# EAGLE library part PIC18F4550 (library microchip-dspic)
PIC18F Flash Microcontroller with USB port
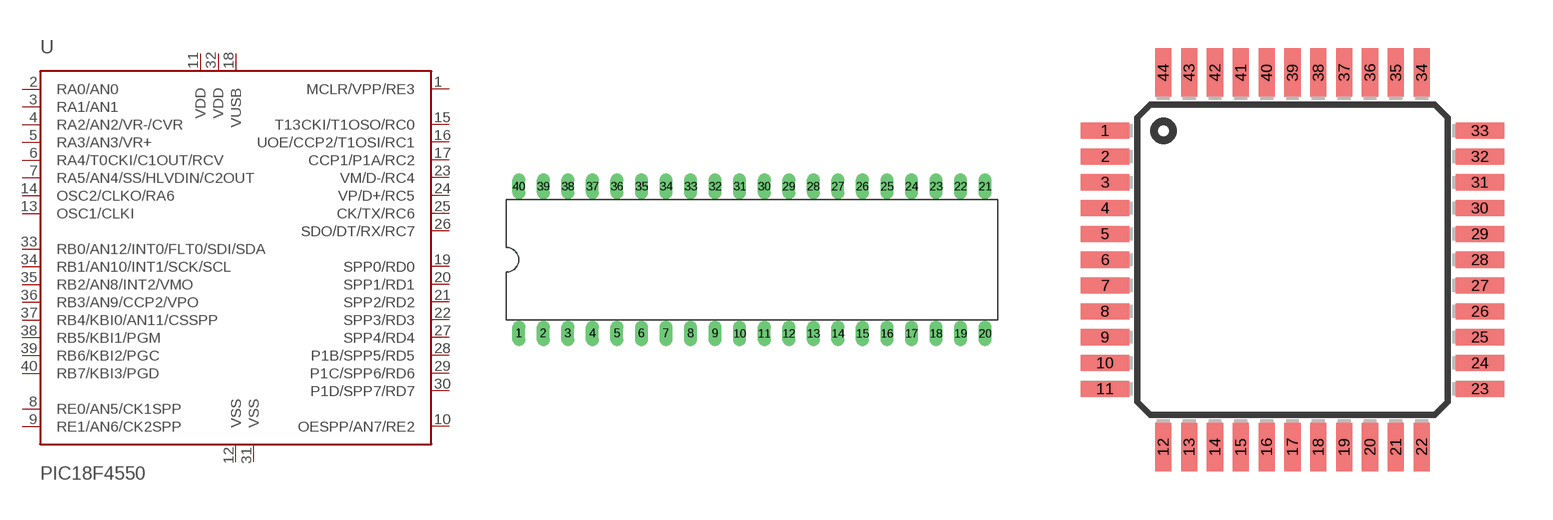
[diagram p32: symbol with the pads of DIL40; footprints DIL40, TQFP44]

Designator prefix -

## PIC18F4550SP  [DIL40]
1  MCLR/VPP/RE3  in
2  RA0/AN0
3  RA1/AN1
4  RA2/AN2/VR-/CVR
5  RA3/AN3/VR+
6  RA4/T0CKI/C1OUT/RCV
7  RA5/AN4/SS/HLVDIN/C2OUT
8  RE0/AN5/CK1SPP
9  RE1/AN6/CK2SPP
10  OESPP/AN7/RE2
11  VDD  pwr
12  VSS  pwr
13  OSC1/CLKI  in
14  OSC2/CLKO/RA6
15  T13CKI/T1OSO/RC0
16  UOE/CCP2/T1OSI/RC1
17  CCP1/P1A/RC2
18  VUSB  pwr
19  SPP0/RD0
20  SPP1/RD1
21  SPP2/RD2
22  SPP3/RD3
23  VM/D-/RC4
24  VP/D+/RC5
25  CK/TX/RC6
26  SDO/DT/RX/RC7
27  SPP4/RD4
28  P1B/SPP5/RD5
29  P1C/SPP6/RD6
30  P1D/SPP7/RD7
31  VSS  pwr
32  VDD  pwr
33  RB0/AN12/INT0/FLT0/SDI/SDA
34  RB1/AN10/INT1/SCK/SCL
35  RB2/AN8/INT2/VMO
36  RB3/AN9/CCP2/VPO
37  RB4/KBI0/AN11/CSSPP
38  RB5/KBI1/PGM
39  RB6/KBI2/PGC
40  RB7/KBI3/PGD

## PIC18F4550TQ-44  [TQFP44]
1  SDO/DT/RX/RC7
2  SPP4/RD4
3  P1B/SPP5/RD5
4  P1C/SPP6/RD6
5  P1D/SPP7/RD7
6  VSS  pwr
7  VDD  pwr
8  RB0/AN12/INT0/FLT0/SDI/SDA
9  RB1/AN10/INT1/SCK/SCL
10  RB2/AN8/INT2/VMO
11  RB3/AN9/CCP2/VPO
14  RB4/KBI0/AN11/CSSPP
15  RB5/KBI1/PGM
16  RB6/KBI2/PGC
17  RB7/KBI3/PGD
18  MCLR/VPP/RE3  in
19  RA0/AN0
20  RA1/AN1
21  RA2/AN2/VR-/CVR
22  RA3/AN3/VR+
23  RA4/T0CKI/C1OUT/RCV
24  RA5/AN4/SS/HLVDIN/C2OUT
25  RE0/AN5/CK1SPP
26  RE1/AN6/CK2SPP
27  OESPP/AN7/RE2
28  VDD  pwr
29  VSS  pwr
30  OSC1/CLKI  in
31  OSC2/CLKO/RA6
32  T13CKI/T1OSO/RC0
35  UOE/CCP2/T1OSI/RC1
36  CCP1/P1A/RC2
37  VUSB  pwr
38  SPP0/RD0
39  SPP1/RD1
40  SPP2/RD2
41  SPP3/RD3
42  VM/D-/RC4
43  VP/D+/RC5
44  CK/TX/RC6

## PIC18F4550ML  [QFN44-8X8]
1  SDO/DT/RX/RC7
2  SPP4/RD4
3  P1B/SPP5/RD5
4  P1C/SPP6/RD6
5  P1D/SPP7/RD7
6  VSS  pwr
8  VDD  pwr
9  RB0/AN12/INT0/FLT0/SDI/SDA
10  RB1/AN10/INT1/SCK/SCL
11  RB2/AN8/INT2/VMO
12  RB3/AN9/CCP2/VPO
14  RB4/KBI0/AN11/CSSPP
15  RB5/KBI1/PGM
16  RB6/KBI2/PGC
17  RB7/KBI3/PGD
18  MCLR/VPP/RE3  in
19  RA0/AN0
20  RA1/AN1
21  RA2/AN2/VR-/CVR
22  RA3/AN3/VR+
23  RA4/T0CKI/C1OUT/RCV
24  RA5/AN4/SS/HLVDIN/C2OUT
25  RE0/AN5/CK1SPP
26  RE1/AN6/CK2SPP
27  OESPP/AN7/RE2
29  VDD  pwr
31  VSS  pwr
32  OSC1/CLKI  in
33  OSC2/CLKO/RA6
34  T13CKI/T1OSO/RC0
35  UOE/CCP2/T1OSI/RC1
36  CCP1/P1A/RC2
37  VUSB  pwr
38  SPP0/RD0
39  SPP1/RD1
40  SPP2/RD2
41  SPP3/RD3
42  VM/D-/RC4
43  VP/D+/RC5
44  CK/TX/RC6

## Footprint DIL40 (pad centres in mm)
Dual In Line package type P
drill 0.813 long: 1 -24.13,-7.62; 2 -21.59,-7.62; 3 -19.05,-7.62; 4 -16.51,-7.62; 5 -13.97,-7.62; 6 -11.43,-7.62; 7 -8.89,-7.62; 8 -6.35,-7.62; 9 -3.81,-7.62; 10 -1.27,-7.62; 11 1.27,-7.62; 12 3.81,-7.62; 13 6.35,-7.62; 14 8.89,-7.62; 15 11.43,-7.62; 16 13.97,-7.62; 17 16.51,-7.62; 18 19.05,-7.62; 19 21.59,-7.62; 20 24.13,-7.62; 21 24.13,7.62; 22 21.59,7.62; 23 19.05,7.62; 24 16.51,7.62; 25 13.97,7.62; 26 11.43,7.62; 27 8.89,7.62; 28 6.35,7.62; 29 3.81,7.62; 30 1.27,7.62; 31 -1.27,7.62; 32 -3.81,7.62; 33 -6.35,7.62; 34 -8.89,7.62; 35 -11.43,7.62; 36 -13.97,7.62; 37 -16.51,7.62; 38 -19.05,7.62; 39 -21.59,7.62; 40 -24.13,7.62

## Footprint TQFP44 (pad centres in mm)
Thin Quad Flat Pack package type TQ
smd 1.5 x 0.5: 1 -5.8,4; 2 -5.8,3.2; 3 -5.8,2.4; 4 -5.8,1.6; 5 -5.8,0.8; 6 -5.8,0; 7 -5.8,-0.8; 8 -5.8,-1.6; 9 -5.8,-2.4; 10 -5.8,-3.2; 11 -5.8,-4; 23 5.8,-4; 24 5.8,-3.2; 25 5.8,-2.4; 26 5.8,-1.6; 27 5.8,-0.8; 28 5.8,0; 29 5.8,0.8; 30 5.8,1.6; 31 5.8,2.4; 32 5.8,3.2; 33 5.8,4
smd 0.5 x 1.5: 12 -4,-5.8; 13 -3.2,-5.8; 14 -2.4,-5.8; 15 -1.6,-5.8; 16 -0.8,-5.8; 17 0,-5.8; 18 0.8,-5.8; 19 1.6,-5.8; 20 2.4,-5.8; 21 3.2,-5.8; 22 4,-5.8; 34 4,5.8; 35 3.2,5.8; 36 2.4,5.8; 37 1.6,5.8; 38 0.8,5.8; 39 0,5.8; 40 -0.8,5.8; 41 -1.6,5.8; 42 -2.4,5.8; 43 -3.2,5.8; 44 -4,5.8

## Footprint QFN44-8X8 (pad centres in mm)
Quad Flat No Lead
smd 0.6 x 0.37: 1 3.825,-3.25; 2 3.825,-2.6; 3 3.825,-1.95; 4 3.825,-1.3; 5 3.825,-0.65; 6 3.825,0; 7 3.825,0.65; 8 3.825,1.3; 9 3.825,1.95; 10 3.825,2.6; 11 3.825,3.25; 23 -3.825,3.25; 24 -3.825,2.6; 25 -3.825,1.95; 26 -3.825,1.3; 27 -3.825,0.65; 28 -3.825,0; 29 -3.825,-0.65; 30 -3.825,-1.3; 31 -3.825,-1.95; 32 -3.825,-2.6; 33 -3.825,-3.25
smd 0.37 x 0.6: 12 3.25,3.825; 13 2.6,3.825; 14 1.95,3.825; 15 1.3,3.825; 16 0.65,3.825; 17 0,3.825; 18 -0.65,3.825; 19 -1.3,3.825; 20 -1.95,3.825; 21 -2.6,3.825; 22 -3.25,3.825; 34 -3.25,-3.825; 35 -2.6,-3.825; 36 -1.95,-3.825; 37 -1.3,-3.825; 38 -0.65,-3.825; 39 0,-3.825; 40 0.65,-3.825; 41 1.3,-3.825; 42 1.95,-3.825; 43 2.6,-3.825; 44 3.25,-3.825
